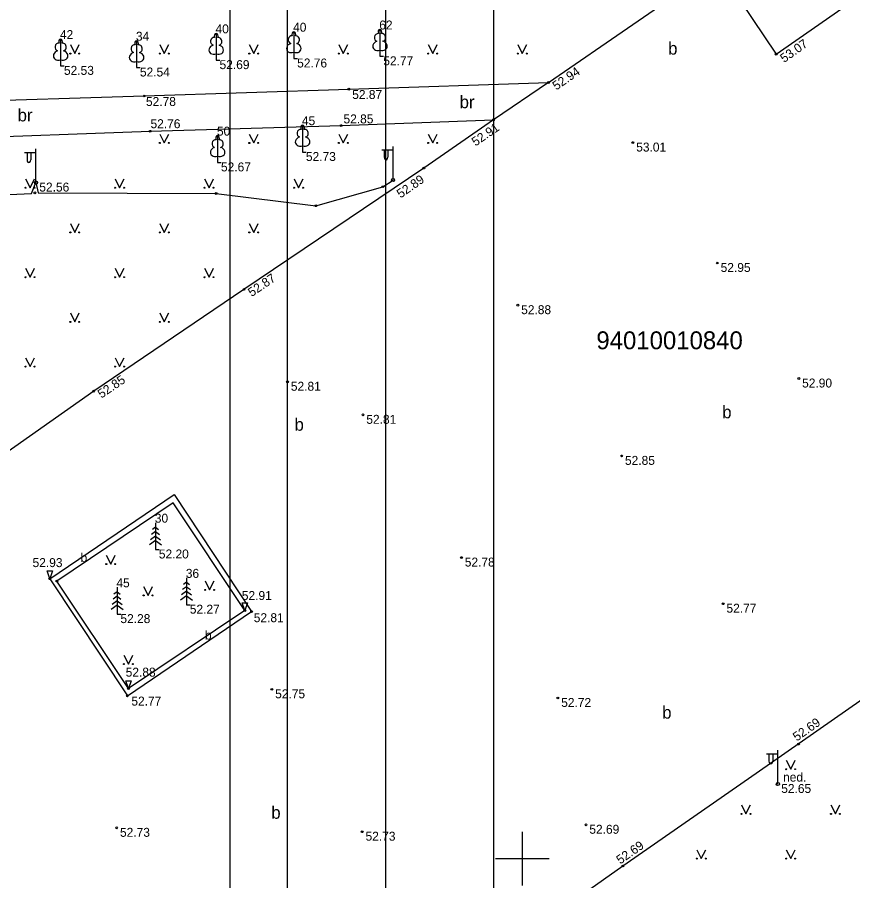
# Model space of a CAD drawing. Extents: x 619806 to 620082, y 405176 to 405386.
# Drawn here: x 619921.79 to 619968.46, y 405248.76 to 405297.03 of the extents above; entities that cross this region are included whole.
import ezdxf

# ---------------------------------------------------------------- set-up
doc = ezdxf.new("R2010")
doc.units = 0
for name, color, linetype in [('APGS_ELEM_####_####_#', 7, 'Continuous'), ('APGS_ELEM_####_TKST_#', 7, 'Continuous'), ('APGS_VADP_ZSPR_####_#', 7, 'Continuous'), ('BUVE_BDET_####_####_#', 7, 'Continuous'), ('BUVE_BDET_####_TKST_#', 7, 'Continuous'), ('CELI_CMAL_####_####_#', 7, 'Continuous'), ('CELI_CSEG_####_TKST_#', 7, 'Continuous'), ('CELI_SEGL_####_####_#', 7, 'Continuous'), ('GEOD_ELEM_####_####_#', 7, 'Continuous'), ('RAMI_PLAN_####_TKST_#', 7, 'Continuous'), ('RELJ_AATZ_####_TKST_#', 7, 'Continuous'), ('RELJ_ELEM_####_####_#', 7, 'Continuous'), ('ROBZ_UZMR_####_TKST_#', 7, 'Continuous'), ('TERT_DIAM_####_TKST_#', 7, 'Continuous'), ('TERT_ELEM_####_####_#', 7, 'Continuous')]:
    doc.layers.add(name, color=color, linetype=linetype)

msp = doc.modelspace()

# ---------------------------------------------------------------- linework, layer by layer
at = {"layer": 'APGS_ELEM_####_####_#'}
for p, q in [((619922.83, 405287.786), (619922.83, 405289.669)), ((619942.781, 405287.929), (619942.781, 405289.812)), ((619922.83, 405289.453), (619922.195, 405289.448)), ((619922.33, 405289.449), (619922.33, 405289.057)), ((619922.54, 405289.451), (619922.54, 405289.057)), ((619942.781, 405289.596), (619942.146, 405289.591)), ((619942.281, 405289.592), (619942.281, 405289.2)), ((619942.491, 405289.594), (619942.491, 405289.2)), ((619964.284, 405254.17), (619964.284, 405256.053)), ((619964.284, 405255.837), (619963.649, 405255.832)), ((619963.784, 405255.833), (619963.784, 405255.441)), ((619963.994, 405255.835), (619963.994, 405255.441))]:
    msp.add_line(p, q, dxfattribs=at)
for centre in [(619922.83, 405287.786), (619942.781, 405287.929), (619964.284, 405254.17)]:
    msp.add_circle(centre, 0.09, dxfattribs=at)
for centre in [(619942.386, 405289.2), (619922.435, 405289.057), (619963.889, 405255.441)]:
    msp.add_ellipse(centre, major_axis=(0, 0.151), ratio=0.695971, start_param=1.570796, end_param=4.712389, dxfattribs=at)
at = {"layer": 'APGS_VADP_ZSPR_####_#'}
msp.add_lwpolyline([(619889.151, 405287.633), (619889.486, 405287.011), (619889.44, 405286.121), (619891.102, 405284.875), (619895.261, 405283.948), (619904.24, 405286.286), (619904.319, 405287.722), (619904.441, 405286.35), (619922.582, 405287.176), (619922.83, 405287.786), (619922.954, 405287.209), (619932.902, 405287.177), (619938.46, 405286.492), (619942.211, 405287.557), (619942.781, 405287.929)], dxfattribs=at)
at = {"layer": 'BUVE_BDET_####_####_#'}
for p, q in [((619923.598, 405265.645), (619930.542, 405270.355)), ((619930.542, 405270.355), (619934.879, 405263.808)), ((619930.494, 405269.879), (619923.997, 405265.515)), ((619934.499, 405263.864), (619930.494, 405269.879)), ((619923.598, 405265.645), (619927.935, 405259.098)), ((619928.002, 405259.5), (619923.997, 405265.515)), ((619927.935, 405259.098), (619934.879, 405263.808)), ((619934.499, 405263.864), (619928.002, 405259.5))]:
    msp.add_line(p, q, dxfattribs=at)
at = {"layer": 'CELI_CMAL_####_####_#'}
for points in [[(619923.8, 405331.651), (619922.909, 405332.209), (619919.472, 405326.95), (619913.839, 405318.4), (619910.247, 405312.462), (619903.419, 405300.947), (619897.856, 405291.596), (619907.48, 405291.973), (619918.115, 405292.304), (619928.883, 405292.628), (619940.313, 405293.006), (619951.468, 405293.381)], [(619951.468, 405293.381), (619960.885, 405299.892), (619964.19, 405294.965), (619971.285, 405299.927), (619977.055, 405303.943), (619973.673, 405308.787), (619991.854, 405321.355)], [(619896.721, 405289.572), (619907.468, 405289.939), (619918, 405290.255), (619929.205, 405290.656), (619939.879, 405290.972), (619948.401, 405291.292), (619944.499, 405288.598), (619934.453, 405281.815), (619926.054, 405276.128), (619919.99, 405271.86), (619920.405, 405271.311), (619919.157, 405270.417), (619919.559, 405269.777), (619917.19, 405268.043), (619917.528, 405267.503), (619917.083, 405267.011)], [(619982.283, 405204.018), (619982.381, 405205.526), (619981.404, 405213.543), (619980.879, 405217.395), (619980.193, 405224.262), (619979.707, 405227.554), (619978.646, 405227.479), (619978.06, 405232.469), (619979.052, 405232.579), (619978.008, 405242.924), (619976.591, 405255.672), (619975.781, 405263.512), (619969.844, 405259.482), (619963.066, 405254.752), (619955.624, 405249.587), (619947.422, 405243.791), (619942.081, 405239.98), (619941.835, 405240.299), (619936.133, 405229.455), (619943.441, 405225.387), (619954.092, 405219.528), (619965.106, 405213.442), (619974.994, 405207.99), (619982.283, 405204.018)]]:
    msp.add_lwpolyline(points, dxfattribs=at)
at = {"layer": 'CELI_SEGL_####_####_#'}
msp.add_lwpolyline([(619951.468, 405293.381), (619948.401, 405291.292)], dxfattribs=at)
at = {"layer": 'GEOD_ELEM_####_####_#'}
for p, q in [((619950, 405251.5), (619950, 405250)), ((619948.5, 405250), (619950, 405250)), ((619950, 405250), (619950, 405248.5)), ((619950, 405250), (619951.5, 405250))]:
    msp.add_line(p, q, dxfattribs=at)
at = {"layer": 'RAMI_PLAN_####_TKST_#'}
msp.add_line((619942.357, 405361.716), (619942.357, 405215.404), dxfattribs=at)
for points in [[(619933.685, 405385.595), (620082.185, 405385.595), (620082.185, 405175.595), (619933.685, 405175.595)], [(619805.793, 405180.095), (619805.793, 405373.209), (619948.393, 405373.209), (619948.393, 405180.095)], [(619936.885, 405180.095), (619936.885, 405373.209), (620079.485, 405373.209), (620079.485, 405180.095)]]:
    msp.add_lwpolyline(points, close=True, dxfattribs=at)
at = {"layer": 'RELJ_ELEM_####_####_#'}
for points in [[(619923.448, 405266.078), (619923.748, 405266.078), (619923.598, 405265.645)], [(619934.349, 405264.297), (619934.649, 405264.297), (619934.499, 405263.864)], [(619927.852, 405259.933), (619928.152, 405259.933), (619928.002, 405259.5)]]:
    msp.add_lwpolyline(points, close=True, dxfattribs=at)
for centre in [(619964.19, 405294.965), (619940.313, 405293.006), (619951.468, 405293.381), (619928.883, 405292.628), (619948.401, 405291.292), (619929.205, 405290.656), (619939.879, 405290.972), (619956.181, 405290.022), (619944.499, 405288.598), (619922.773, 405287.214), (619932.902, 405287.177), (619942.211, 405287.557), (619938.46, 405286.492), (619960.899, 405283.291), (619934.453, 405281.815), (619949.753, 405280.932), (619936.885, 405276.652), (619965.451, 405276.833), (619926.054, 405276.128), (619941.102, 405274.803), (619955.554, 405272.509), (619946.603, 405266.825), (619923.598, 405265.645), (619923.997, 405265.515), (619961.225, 405264.246), (619934.499, 405263.864), (619934.879, 405263.808), (619928.002, 405259.5), (619936.008, 405259.462), (619927.935, 405259.098), (619951.99, 405258.978), (619965.437, 405256.401), (619927.339, 405251.719), (619941.058, 405251.504), (619953.562, 405251.89), (619955.624, 405249.587)]:
    msp.add_circle(centre, 0.05, dxfattribs=at)
at = {"layer": 'TERT_ELEM_####_####_#'}
for p, q in [((619924.75, 405295.5), (619925, 405295)), ((619925, 405295), (619925.25, 405295.5)), ((619929.75, 405295.5), (619930, 405295)), ((619930, 405295), (619930.25, 405295.5)), ((619934.75, 405295.5), (619935, 405295)), ((619935, 405295), (619935.25, 405295.5)), ((619939.75, 405295.5), (619940, 405295)), ((619940, 405295), (619940.25, 405295.5)), ((619944.75, 405295.5), (619945, 405295)), ((619945, 405295), (619945.25, 405295.5)), ((619949.75, 405295.5), (619950, 405295)), ((619950, 405295), (619950.25, 405295.5)), ((619932.901, 405294.976), (619932.901, 405294.629)), ((619937.236, 405295.068), (619937.236, 405294.721)), ((619942.05, 405295.191), (619942.05, 405294.844)), ((619924.207, 405294.656), (619924.207, 405294.309)), ((619928.452, 405294.564), (619928.452, 405294.217)), ((619932.901, 405294.629), (619933.101, 405294.629)), ((619937.236, 405294.721), (619937.436, 405294.721)), ((619942.05, 405294.844), (619942.25, 405294.844)), ((619924.207, 405294.309), (619924.407, 405294.309)), ((619928.452, 405294.217), (619928.652, 405294.217)), ((619929.75, 405290.5), (619930, 405290)), ((619930, 405290), (619930.25, 405290.5)), ((619934.75, 405290.5), (619935, 405290)), ((619935, 405290), (619935.25, 405290.5)), ((619939.75, 405290.5), (619940, 405290)), ((619940, 405290), (619940.25, 405290.5)), ((619944.75, 405290.5), (619945, 405290)), ((619945, 405290), (619945.25, 405290.5)), ((619937.727, 405289.841), (619937.727, 405289.494)), ((619932.98, 405289.258), (619932.98, 405288.911)), ((619937.727, 405289.494), (619937.927, 405289.494)), ((619932.98, 405288.911), (619933.18, 405288.911)), ((619922.25, 405288), (619922.5, 405287.5)), ((619922.5, 405287.5), (619922.75, 405288)), ((619927.25, 405288), (619927.5, 405287.5)), ((619927.5, 405287.5), (619927.75, 405288)), ((619932.25, 405288), (619932.5, 405287.5)), ((619932.5, 405287.5), (619932.75, 405288)), ((619937.25, 405288), (619937.5, 405287.5)), ((619937.5, 405287.5), (619937.75, 405288)), ((619924.75, 405285.5), (619925, 405285)), ((619925, 405285), (619925.25, 405285.5)), ((619929.75, 405285.5), (619930, 405285)), ((619930, 405285), (619930.25, 405285.5)), ((619934.75, 405285.5), (619935, 405285)), ((619935, 405285), (619935.25, 405285.5)), ((619922.25, 405283), (619922.5, 405282.5)), ((619922.5, 405282.5), (619922.75, 405283)), ((619927.25, 405283), (619927.5, 405282.5)), ((619927.5, 405282.5), (619927.75, 405283)), ((619932.25, 405283), (619932.5, 405282.5)), ((619932.5, 405282.5), (619932.75, 405283)), ((619924.75, 405280.5), (619925, 405280)), ((619925, 405280), (619925.25, 405280.5)), ((619929.75, 405280.5), (619930, 405280)), ((619930, 405280), (619930.25, 405280.5)), ((619922.25, 405278), (619922.5, 405277.5)), ((619922.5, 405277.5), (619922.75, 405278)), ((619927.25, 405278), (619927.5, 405277.5)), ((619927.5, 405277.5), (619927.75, 405278)), ((619929.509, 405268.528), (619929.333, 405268.4)), ((619929.509, 405268.778), (619929.509, 405267.278)), ((619929.509, 405268.528), (619929.683, 405268.4)), ((619929.509, 405268.028), (619929.231, 405267.824)), ((619929.509, 405268.278), (619929.293, 405268.12)), ((619929.509, 405268.278), (619929.725, 405268.12)), ((619929.509, 405268.028), (619929.787, 405267.824)), ((619929.509, 405267.778), (619929.177, 405267.534)), ((619929.509, 405267.778), (619929.843, 405267.534)), ((619926.76, 405266.964), (619927.01, 405266.464)), ((619927.01, 405266.464), (619927.26, 405266.964)), ((619929.509, 405267.278), (619929.709, 405267.278)), ((619931.24, 405265.694), (619931.24, 405264.194)), ((619932.284, 405265.52), (619932.534, 405265.02)), ((619932.534, 405265.02), (619932.784, 405265.52)), ((619927.362, 405265.165), (619927.362, 405263.665)), ((619928.846, 405265.209), (619929.096, 405264.709)), ((619929.096, 405264.709), (619929.346, 405265.209)), ((619931.24, 405265.194), (619931.024, 405265.036)), ((619931.24, 405265.444), (619931.064, 405265.316)), ((619931.24, 405265.444), (619931.414, 405265.316)), ((619931.24, 405265.194), (619931.456, 405265.036)), ((619927.362, 405264.665), (619927.146, 405264.507)), ((619927.362, 405264.915), (619927.186, 405264.787)), ((619927.362, 405264.915), (619927.536, 405264.787)), ((619927.362, 405264.665), (619927.578, 405264.507)), ((619931.24, 405264.694), (619930.908, 405264.45)), ((619931.24, 405264.944), (619930.962, 405264.74)), ((619931.24, 405264.944), (619931.518, 405264.74)), ((619931.24, 405264.694), (619931.574, 405264.45)), ((619927.362, 405264.165), (619927.03, 405263.921)), ((619927.362, 405264.415), (619927.084, 405264.211)), ((619927.362, 405264.415), (619927.64, 405264.211)), ((619927.362, 405264.165), (619927.696, 405263.921)), ((619931.24, 405264.194), (619931.44, 405264.194)), ((619927.362, 405263.665), (619927.562, 405263.665)), ((619927.741, 405261.377), (619927.991, 405260.877)), ((619927.991, 405260.877), (619928.241, 405261.377)), ((619964.75, 405255.5), (619965, 405255)), ((619965, 405255), (619965.25, 405255.5)), ((619962.25, 405253), (619962.5, 405252.5)), ((619962.5, 405252.5), (619962.75, 405253)), ((619967.25, 405253), (619967.5, 405252.5)), ((619967.5, 405252.5), (619967.75, 405253)), ((619959.75, 405250.5), (619960, 405250)), ((619960, 405250), (619960.25, 405250.5)), ((619964.75, 405250.5), (619965, 405250)), ((619965, 405250), (619965.25, 405250.5))]:
    msp.add_line(p, q, dxfattribs=at)
for points in [[(619932.901, 405296.129), (619932.901, 405294.976)], [(619932.991, 405295.897), (619932.99, 405295.898)], [(619937.236, 405296.221), (619937.236, 405295.068)], [(619937.326, 405295.989), (619937.325, 405295.99)], [(619942.05, 405296.344), (619942.05, 405295.191)], [(619942.14, 405296.112), (619942.139, 405296.113)], [(619924.207, 405295.809), (619924.207, 405294.656)], [(619924.297, 405295.577), (619924.296, 405295.578)], [(619928.452, 405295.717), (619928.452, 405294.564)], [(619928.542, 405295.485), (619928.541, 405295.486)], [(619937.727, 405290.994), (619937.727, 405289.841)], [(619937.817, 405290.762), (619937.816, 405290.763)], [(619932.98, 405290.411), (619932.98, 405289.258)], [(619933.07, 405290.179), (619933.069, 405290.18)]]:
    msp.add_lwpolyline(points, dxfattribs=at)
for centre, radius in [((619924.75, 405295), 0.028), ((619925.25, 405295), 0.0263), ((619929.75, 405295), 0.028), ((619930.25, 405295), 0.0263), ((619934.75, 405295), 0.028), ((619935.25, 405295), 0.0263), ((619939.75, 405295), 0.028), ((619940.25, 405295), 0.0263), ((619944.75, 405295), 0.028), ((619945.25, 405295), 0.0263), ((619949.75, 405295), 0.028), ((619950.25, 405295), 0.0263), ((619929.75, 405290), 0.028), ((619930.25, 405290), 0.0263), ((619934.75, 405290), 0.028), ((619935.25, 405290), 0.0263), ((619939.75, 405290), 0.028), ((619940.25, 405290), 0.0263), ((619944.75, 405290), 0.028), ((619945.25, 405290), 0.0263), ((619922.25, 405287.5), 0.028), ((619922.75, 405287.5), 0.0263), ((619927.25, 405287.5), 0.028), ((619927.75, 405287.5), 0.0263), ((619932.25, 405287.5), 0.028), ((619932.75, 405287.5), 0.0263), ((619937.25, 405287.5), 0.028), ((619937.75, 405287.5), 0.0263), ((619924.75, 405285), 0.028), ((619925.25, 405285), 0.0263), ((619929.75, 405285), 0.028), ((619930.25, 405285), 0.0263), ((619934.75, 405285), 0.028), ((619935.25, 405285), 0.0263), ((619922.25, 405282.5), 0.028), ((619922.75, 405282.5), 0.0263), ((619927.25, 405282.5), 0.028), ((619927.75, 405282.5), 0.0263), ((619932.25, 405282.5), 0.028), ((619932.75, 405282.5), 0.0263), ((619924.75, 405280), 0.028), ((619925.25, 405280), 0.0263), ((619929.75, 405280), 0.028), ((619930.25, 405280), 0.0263), ((619922.25, 405277.5), 0.028), ((619922.75, 405277.5), 0.0263), ((619927.25, 405277.5), 0.028), ((619927.75, 405277.5), 0.0263), ((619926.76, 405266.464), 0.028), ((619927.26, 405266.464), 0.0263), ((619932.284, 405265.019), 0.028), ((619932.784, 405265.019), 0.0263), ((619928.846, 405264.709), 0.028), ((619929.346, 405264.709), 0.0263), ((619927.741, 405260.876), 0.028), ((619928.241, 405260.876), 0.0263), ((619964.75, 405255), 0.028), ((619965.25, 405255), 0.0263), ((619962.25, 405252.5), 0.028), ((619962.75, 405252.5), 0.0263), ((619967.25, 405252.5), 0.028), ((619967.75, 405252.5), 0.0263), ((619959.75, 405250), 0.028), ((619960.25, 405250), 0.0263), ((619964.75, 405250), 0.028), ((619965.25, 405250), 0.0263)]:
    msp.add_circle(centre, radius, dxfattribs=at)
for centre, major_axis, ratio, start_param, end_param in [((619932.773, 405295.684), (-0.039, -0.212), 0.861323, 3.141593, 6.283185), ((619932.901, 405295.979), (0, -0.15), 0.707107, 3.14537, 5.287485), ((619932.901, 405295.979), (0, -0.15), 0.707107, 0.995701, 3.137816), ((619933.029, 405295.684), (0.039, -0.212), 0.861323, 0, 3.141593), ((619937.108, 405295.776), (-0.039, -0.212), 0.861323, 3.141593, 6.283185), ((619937.236, 405296.071), (0, -0.15), 0.707107, 3.14537, 5.287485), ((619937.236, 405296.071), (0, -0.15), 0.707107, 0.995701, 3.137816), ((619937.364, 405295.776), (0.039, -0.212), 0.861323, 0, 3.141593), ((619941.922, 405295.899), (-0.039, -0.212), 0.861323, 3.141593, 6.283185), ((619942.05, 405296.194), (0, -0.15), 0.707107, 3.14537, 5.287485), ((619942.05, 405296.194), (0, -0.15), 0.707107, 0.995701, 3.137816), ((619942.178, 405295.899), (0.039, -0.212), 0.861323, 0, 3.141593), ((619924.079, 405295.364), (-0.039, -0.212), 0.861323, 3.141593, 6.283185), ((619924.207, 405295.659), (0, -0.15), 0.707107, 3.14537, 5.287485), ((619924.207, 405295.659), (0, -0.15), 0.707107, 0.995701, 3.137816), ((619924.335, 405295.364), (0.039, -0.212), 0.861323, 0, 3.141593), ((619928.324, 405295.272), (-0.039, -0.212), 0.861323, 3.141593, 6.283185), ((619928.452, 405295.567), (0, -0.15), 0.707107, 3.14537, 5.287485), ((619928.452, 405295.567), (0, -0.15), 0.707107, 0.995701, 3.137816), ((619928.58, 405295.272), (0.039, -0.212), 0.861323, 0, 3.141593), ((619932.811, 405295.222), (0.307, 0.095), 0.814445, 1.570796, 4.752015), ((619932.991, 405295.222), (-0.307, 0.095), 0.814445, 1.531171, 4.712389), ((619937.146, 405295.314), (0.307, 0.095), 0.814445, 1.570796, 4.752015), ((619937.326, 405295.314), (-0.307, 0.095), 0.814445, 1.531171, 4.712389), ((619941.96, 405295.437), (0.307, 0.095), 0.814445, 1.570796, 4.752015), ((619942.14, 405295.437), (-0.307, 0.095), 0.814445, 1.531171, 4.712389), ((619924.117, 405294.902), (0.307, 0.095), 0.814445, 1.570796, 4.752015), ((619924.297, 405294.902), (-0.307, 0.095), 0.814445, 1.531171, 4.712389), ((619928.362, 405294.81), (0.307, 0.095), 0.814445, 1.570796, 4.752015), ((619928.542, 405294.81), (-0.307, 0.095), 0.814445, 1.531171, 4.712389), ((619937.599, 405290.549), (-0.039, -0.212), 0.861323, 3.141593, 6.283185), ((619937.727, 405290.844), (0, -0.15), 0.707107, 3.14537, 5.287485), ((619937.727, 405290.844), (0, -0.15), 0.707107, 0.995701, 3.137816), ((619937.855, 405290.549), (0.039, -0.212), 0.861323, 0, 3.141593), ((619932.852, 405289.966), (-0.039, -0.212), 0.861323, 3.141593, 6.283185), ((619932.98, 405290.261), (0, -0.15), 0.707107, 3.14537, 5.287485), ((619932.98, 405290.261), (0, -0.15), 0.707107, 0.995701, 3.137816), ((619933.108, 405289.966), (0.039, -0.212), 0.861323, 0, 3.141593), ((619937.637, 405290.087), (0.307, 0.095), 0.814445, 1.570796, 4.752015), ((619937.817, 405290.087), (-0.307, 0.095), 0.814445, 1.531171, 4.712389), ((619932.89, 405289.504), (0.307, 0.095), 0.814445, 1.570796, 4.752015), ((619933.07, 405289.504), (-0.307, 0.095), 0.814445, 1.531171, 4.712389)]:
    msp.add_ellipse(centre, major_axis=major_axis, ratio=ratio, start_param=start_param, end_param=end_param, dxfattribs=at)

# ---------------------------------------------------------------- texts
at = {"layer": 'APGS_ELEM_####_TKST_#'}
msp.add_text('ned.', height=0.5, dxfattribs=at).set_placement((619964.574, 405254.305))
at = {"layer": 'BUVE_BDET_####_TKST_#'}
for p in [(619925.32, 405266.575), (619932.271, 405262.242)]:
    msp.add_text('b', height=0.5, dxfattribs=at).set_placement(p)
at = {"layer": 'CELI_CSEG_####_TKST_#'}
for s, p in [('b', (619958.152, 405294.94)), ('br', (619946.502, 405291.944)), ('br', (619921.804, 405291.207)), ('b', (619961.173, 405274.613)), ('b', (619937.277, 405273.917)), ('b', (619957.82, 405257.825)), ('b', (619935.978, 405252.229))]:
    msp.add_text(s, height=0.7, dxfattribs=at).set_placement(p)
at = {"layer": 'RELJ_AATZ_####_TKST_#'}
for s, rotation, p in [(' 53.07', 34.9676, (619964.477, 405294.362)), (' 52.94', 34.6603, (619951.752, 405292.822)), (' 52.91', 34.2596, (619947.233, 405289.695)), (' 52.89', 34.6218, (619943.049, 405286.791)), (' 52.87', 34.027, (619934.733, 405281.282)), (' 52.85', 34.1021, (619926.334, 405275.604)), (' 52.69', 34.958, (619965.186, 405256.433)), (' 52.69', 34.762, (619955.32, 405249.56))]:
    msp.add_text(s, height=0.5, rotation=rotation, dxfattribs=at).set_placement(p)
for s, p in [(' 52.69', (619932.901, 405294.129)), (' 52.76', (619937.236, 405294.221)), (' 52.77', (619942.05, 405294.344)), (' 52.53', (619924.207, 405293.809)), (' 52.54', (619928.452, 405293.717)), (' 52.78', (619928.79, 405292.069)), (' 52.87', (619940.313, 405292.46)), (' 52.85', (619939.826, 405291.095)), (' 52.76', (619929.043, 405290.827)), (' 53.01', (619956.181, 405289.522)), (' 52.73', (619937.727, 405288.994)), (' 52.67', (619932.98, 405288.411)), (' 52.56', (619922.83, 405287.286)), (' 52.95', (619960.899, 405282.791)), (' 52.88', (619949.753, 405280.432)), (' 52.81', (619936.885, 405276.152)), (' 52.90', (619965.451, 405276.333)), (' 52.81', (619941.102, 405274.303)), (' 52.85', (619955.554, 405272.009)), (' 52.20', (619929.509, 405266.778)), (' 52.93', (619922.453, 405266.295)), (' 52.78', (619946.603, 405266.325)), (' 52.91', (619934.146, 405264.455)), (' 52.27', (619931.24, 405263.694)), (' 52.77', (619961.225, 405263.746)), (' 52.28', (619927.362, 405263.165)), (' 52.81', (619934.813, 405263.216)), (' 52.88', (619927.657, 405260.172)), (' 52.75', (619936.008, 405258.962)), (' 52.77', (619927.975, 405258.556)), (' 52.72', (619951.99, 405258.478)), (' 52.65', (619964.284, 405253.67)), (' 52.73', (619927.339, 405251.219)), (' 52.73', (619941.058, 405251.004)), (' 52.69', (619953.562, 405251.39))]:
    msp.add_text(s, height=0.5, dxfattribs=at).set_placement(p)
at = {"layer": 'ROBZ_UZMR_####_TKST_#'}
msp.add_text('94010010840', height=1, dxfattribs=at).set_placement((619954.142, 405278.471))
at = {"layer": 'TERT_DIAM_####_TKST_#'}
for s, p in [(' 40', (619932.676, 405296.129)), (' 40', (619937.011, 405296.221)), (' 62', (619941.825, 405296.344)), (' 42', (619923.982, 405295.809)), (' 34', (619928.227, 405295.717)), (' 45', (619937.502, 405290.994)), (' 50', (619932.755, 405290.411)), (' 30', (619929.284, 405268.778)), (' 36', (619931.015, 405265.694)), (' 45', (619927.137, 405265.165))]:
    msp.add_text(s, height=0.5, dxfattribs=at).set_placement(p)

doc.saveas('drawing.dxf')
